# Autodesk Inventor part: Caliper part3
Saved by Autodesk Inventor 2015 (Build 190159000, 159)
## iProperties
Created: 2015-04
Part Number: Caliper part3
Material: Generic
Document SubType Name: Modeling
Designer: Gabriel Cabellos
Density: 1 g/cm^3
Appearance: Default
Author: Gabriel Cabellos
Sending System: SolidWorks 2011
Last Author: Pets
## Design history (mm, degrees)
node "Caliper part3.ipt1"
node "Chamfer1"
node "Base1"
